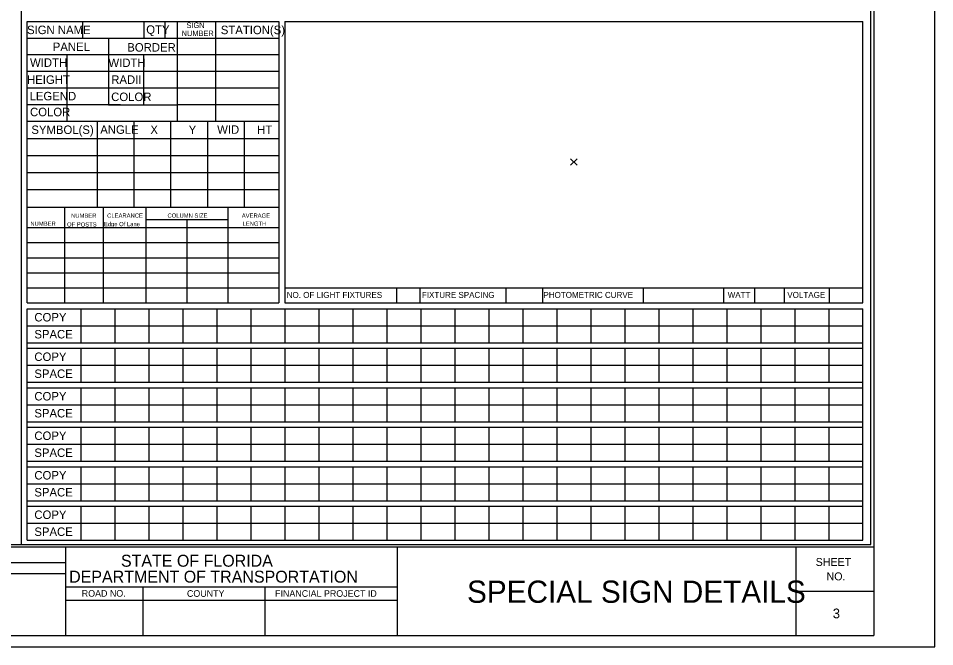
# Model space of a CAD drawing. Extents: x 17890628 to 17891459, y 17897314 to 17897992.
# Drawn here: x 17890765.8 to 17890830.7, y 17897413.7 to 17897458.2 of the extents above; entities that cross this region are included whole.
import ezdxf

# ---------------------------------------------------------------- set-up
doc = ezdxf.new("R2010")
doc.units = 0
for name, color, linetype in [('NonPlottingEle_dp', 7, 'Continuous'), ('PlotBorder_dp', 7, 'Continuous'), ('SheetBorder_dp', 7, 'Continuous'), ('SheetLines_dp', 7, 'Continuous'), ('SheetLinesMisc2_dp', 7, 'Continuous'), ('TextMinor', 7, 'Continuous'), ('TextMisc', 7, 'Continuous'), ('TextShtNo', 7, 'Continuous')]:
    doc.layers.add(name, color=color, linetype=linetype)

msp = doc.modelspace()

# ---------------------------------------------------------------- linework, layer by layer
at = {"layer": 'NonPlottingEle_dp'}
for p, q in [((17890804.948, 17897448.239), (17890805.414, 17897447.773)), ((17890804.948, 17897447.773), (17890805.414, 17897448.239))]:
    msp.add_line(p, q, dxfattribs=at)
at = {"layer": 'PlotBorder_dp'}
msp.add_lwpolyline([(17890701.346, 17897413.687), (17890830.745, 17897413.687), (17890830.745, 17897496.818), (17890701.346, 17897496.818)], close=True, dxfattribs=at)
at = {"layer": 'SheetBorder_dp'}
for p, q in [((17890826.432, 17897496.034), (17890826.432, 17897414.472)), ((17890705.659, 17897420.746), (17890826.432, 17897420.746)), ((17890705.659, 17897414.472), (17890826.432, 17897414.472))]:
    msp.add_line(p, q, dxfattribs=at)
at = {"layer": 'SheetLines_dp'}
for p, q in [((17890769.182, 17897420.746), (17890769.182, 17897414.472)), ((17890792.71, 17897414.471), (17890792.71, 17897420.745)), ((17890820.943, 17897414.471), (17890820.943, 17897420.745)), ((17890705.659, 17897419.648), (17890769.182, 17897419.648)), ((17890705.659, 17897418.864), (17890769.182, 17897418.864)), ((17890769.182, 17897417.923), (17890792.71, 17897417.923)), ((17890774.672, 17897417.923), (17890774.672, 17897414.472)), ((17890783.299, 17897417.923), (17890783.299, 17897414.472)), ((17890820.942, 17897417.609), (17890826.432, 17897417.609)), ((17890769.182, 17897416.981), (17890792.71, 17897416.981))]:
    msp.add_line(p, q, dxfattribs=at)
at = {"layer": 'SheetLinesMisc2_dp'}
for p, q in [((17890766.047, 17897495.849), (17890766.047, 17897420.931)), ((17890826.223, 17897420.931), (17890826.223, 17897495.848)), ((17890766.46, 17897438.022), (17890766.46, 17897457.96)), ((17890766.46, 17897457.96), (17890784.305, 17897457.96)), ((17890770.394, 17897457.96), (17890770.394, 17897456.783)), ((17890774.731, 17897457.96), (17890774.731, 17897456.783)), ((17890776.213, 17897457.96), (17890776.213, 17897456.783)), ((17890777.096, 17897457.96), (17890777.096, 17897450.894)), ((17890779.811, 17897457.96), (17890779.811, 17897450.894)), ((17890784.305, 17897457.96), (17890784.305, 17897438.022)), ((17890784.715, 17897457.96), (17890825.647, 17897457.96)), ((17890784.715, 17897457.96), (17890784.715, 17897438.051)), ((17890825.647, 17897438.051), (17890825.647, 17897457.962)), ((17890766.46, 17897456.783), (17890784.305, 17897456.783)), ((17890772.227, 17897456.783), (17890772.227, 17897452.059)), ((17890766.46, 17897455.605), (17890784.305, 17897455.605)), ((17890769.28, 17897455.605), (17890769.28, 17897450.894)), ((17890774.716, 17897455.592), (17890774.716, 17897452.059)), ((17890766.46, 17897454.427), (17890784.305, 17897454.427)), ((17890766.46, 17897453.25), (17890784.305, 17897453.25)), ((17890766.46, 17897452.072), (17890773.078, 17897452.072)), ((17890772.227, 17897452.059), (17890777.096, 17897452.059)), ((17890777.096, 17897452.072), (17890784.305, 17897452.072)), ((17890766.46, 17897450.894), (17890784.305, 17897450.894)), ((17890771.416, 17897450.871), (17890771.416, 17897444.858)), ((17890774.023, 17897450.871), (17890774.023, 17897444.858)), ((17890776.631, 17897450.871), (17890776.631, 17897444.858)), ((17890779.238, 17897450.871), (17890779.238, 17897444.858)), ((17890781.845, 17897450.871), (17890781.845, 17897444.858)), ((17890766.464, 17897449.668), (17890784.305, 17897449.668)), ((17890766.464, 17897448.466), (17890784.305, 17897448.466)), ((17890766.464, 17897447.263), (17890784.305, 17897447.263)), ((17890766.464, 17897446.061), (17890784.305, 17897446.061)), ((17890766.46, 17897444.801), (17890784.305, 17897444.801)), ((17890769.108, 17897444.801), (17890769.108, 17897438.022)), ((17890771.845, 17897444.801), (17890771.845, 17897438.022)), ((17890774.867, 17897444.801), (17890774.867, 17897438.022)), ((17890780.687, 17897444.801), (17890780.687, 17897438.022)), ((17890774.867, 17897443.939), (17890780.682, 17897443.939)), ((17890777.789, 17897443.939), (17890777.789, 17897438.022)), ((17890766.46, 17897443.363), (17890784.305, 17897443.363)), ((17890766.46, 17897442.295), (17890784.305, 17897442.295)), ((17890766.46, 17897441.227), (17890784.305, 17897441.227)), ((17890766.46, 17897440.159), (17890784.305, 17897440.159)), ((17890766.46, 17897439.091), (17890784.305, 17897439.091)), ((17890784.715, 17897439.091), (17890825.647, 17897439.091)), ((17890792.621, 17897439.091), (17890792.621, 17897438.023)), ((17890794.278, 17897439.091), (17890794.278, 17897438.023)), ((17890800.373, 17897439.091), (17890800.373, 17897438.023)), ((17890802.967, 17897439.091), (17890802.967, 17897438.023)), ((17890810.093, 17897439.091), (17890810.093, 17897438.023)), ((17890815.782, 17897439.091), (17890815.782, 17897438.023)), ((17890817.978, 17897439.091), (17890817.978, 17897438.023)), ((17890820.095, 17897439.091), (17890820.095, 17897438.023)), ((17890823.283, 17897439.091), (17890823.283, 17897438.023)), ((17890766.46, 17897438.022), (17890784.305, 17897438.022)), ((17890784.715, 17897438.051), (17890784.715, 17897438.024)), ((17890784.715, 17897438.023), (17890825.647, 17897438.023)), ((17890825.647, 17897438.024), (17890825.647, 17897438.051)), ((17890766.458, 17897437.612), (17890825.647, 17897437.612)), ((17890766.458, 17897421.223), (17890766.458, 17897437.612)), ((17890770.269, 17897437.612), (17890770.269, 17897435.207)), ((17890772.677, 17897437.612), (17890772.677, 17897435.207)), ((17890775.084, 17897437.612), (17890775.084, 17897435.207)), ((17890777.492, 17897437.612), (17890777.492, 17897435.207)), ((17890779.9, 17897437.612), (17890779.9, 17897435.207)), ((17890782.308, 17897437.612), (17890782.308, 17897435.207)), ((17890784.715, 17897437.612), (17890784.715, 17897435.207)), ((17890787.123, 17897437.612), (17890787.123, 17897435.207)), ((17890789.531, 17897437.612), (17890789.531, 17897435.207)), ((17890791.939, 17897437.612), (17890791.939, 17897435.207)), ((17890794.347, 17897437.612), (17890794.347, 17897435.207)), ((17890796.754, 17897437.612), (17890796.754, 17897435.207)), ((17890799.162, 17897437.612), (17890799.162, 17897435.207)), ((17890801.57, 17897437.612), (17890801.57, 17897435.207)), ((17890803.977, 17897437.612), (17890803.977, 17897435.207)), ((17890806.385, 17897437.612), (17890806.385, 17897435.207)), ((17890808.793, 17897437.612), (17890808.793, 17897435.207)), ((17890811.201, 17897437.612), (17890811.201, 17897435.207)), ((17890813.608, 17897437.612), (17890813.608, 17897435.207)), ((17890816.016, 17897437.612), (17890816.016, 17897435.207)), ((17890818.424, 17897437.612), (17890818.424, 17897435.207)), ((17890820.832, 17897437.612), (17890820.832, 17897435.207)), ((17890823.239, 17897437.612), (17890823.239, 17897435.207)), ((17890825.647, 17897421.223), (17890825.647, 17897437.612)), ((17890766.458, 17897436.411), (17890825.647, 17897436.411)), ((17890766.458, 17897435.207), (17890825.647, 17897435.207)), ((17890766.458, 17897434.815), (17890825.647, 17897434.815)), ((17890770.269, 17897434.815), (17890770.269, 17897432.41)), ((17890772.677, 17897434.815), (17890772.677, 17897432.41)), ((17890775.084, 17897434.815), (17890775.084, 17897432.41)), ((17890777.492, 17897434.815), (17890777.492, 17897432.41)), ((17890779.9, 17897434.815), (17890779.9, 17897432.41)), ((17890782.308, 17897434.815), (17890782.308, 17897432.41)), ((17890784.715, 17897434.815), (17890784.715, 17897432.41)), ((17890787.123, 17897434.815), (17890787.123, 17897432.41)), ((17890789.531, 17897434.815), (17890789.531, 17897432.41)), ((17890791.939, 17897434.815), (17890791.939, 17897432.41)), ((17890794.347, 17897434.815), (17890794.347, 17897432.41)), ((17890796.754, 17897434.815), (17890796.754, 17897432.41)), ((17890799.162, 17897434.815), (17890799.162, 17897432.41)), ((17890801.57, 17897434.815), (17890801.57, 17897432.41)), ((17890803.977, 17897434.815), (17890803.977, 17897432.41)), ((17890806.385, 17897434.815), (17890806.385, 17897432.41)), ((17890808.793, 17897434.815), (17890808.793, 17897432.41)), ((17890811.201, 17897434.815), (17890811.201, 17897432.41)), ((17890813.608, 17897434.815), (17890813.608, 17897432.41)), ((17890816.016, 17897434.815), (17890816.016, 17897432.41)), ((17890818.424, 17897434.815), (17890818.424, 17897432.41)), ((17890820.832, 17897434.815), (17890820.832, 17897432.41)), ((17890823.239, 17897434.815), (17890823.239, 17897432.41)), ((17890766.458, 17897433.613), (17890825.647, 17897433.613)), ((17890766.458, 17897432.41), (17890825.647, 17897432.41)), ((17890766.458, 17897432.018), (17890825.647, 17897432.018)), ((17890770.269, 17897432.018), (17890770.269, 17897429.614)), ((17890772.677, 17897432.018), (17890772.677, 17897429.614)), ((17890775.084, 17897432.018), (17890775.084, 17897429.614)), ((17890777.492, 17897432.018), (17890777.492, 17897429.614)), ((17890779.9, 17897432.018), (17890779.9, 17897429.614)), ((17890782.308, 17897432.018), (17890782.308, 17897429.614)), ((17890784.715, 17897432.018), (17890784.715, 17897429.614)), ((17890787.123, 17897432.018), (17890787.123, 17897429.614)), ((17890789.531, 17897432.018), (17890789.531, 17897429.614)), ((17890791.939, 17897432.018), (17890791.939, 17897429.614)), ((17890794.347, 17897432.018), (17890794.347, 17897429.614)), ((17890796.754, 17897432.018), (17890796.754, 17897429.614)), ((17890799.162, 17897432.018), (17890799.162, 17897429.614)), ((17890801.57, 17897432.018), (17890801.57, 17897429.614)), ((17890803.977, 17897432.018), (17890803.977, 17897429.614)), ((17890806.385, 17897432.018), (17890806.385, 17897429.614)), ((17890808.793, 17897432.018), (17890808.793, 17897429.614)), ((17890811.201, 17897432.018), (17890811.201, 17897429.614)), ((17890813.608, 17897432.018), (17890813.608, 17897429.614)), ((17890816.016, 17897432.018), (17890816.016, 17897429.614)), ((17890818.424, 17897432.018), (17890818.424, 17897429.614)), ((17890820.832, 17897432.018), (17890820.832, 17897429.614)), ((17890823.239, 17897432.018), (17890823.239, 17897429.614)), ((17890766.458, 17897430.816), (17890825.647, 17897430.816)), ((17890766.458, 17897429.614), (17890825.647, 17897429.614)), ((17890766.458, 17897429.221), (17890825.647, 17897429.221)), ((17890770.269, 17897429.221), (17890770.269, 17897426.817)), ((17890772.677, 17897429.221), (17890772.677, 17897426.817)), ((17890775.084, 17897429.221), (17890775.084, 17897426.817)), ((17890777.492, 17897429.221), (17890777.492, 17897426.817)), ((17890779.9, 17897429.221), (17890779.9, 17897426.817)), ((17890782.308, 17897429.221), (17890782.308, 17897426.817)), ((17890784.715, 17897429.221), (17890784.715, 17897426.817)), ((17890787.123, 17897429.221), (17890787.123, 17897426.817)), ((17890789.531, 17897429.221), (17890789.531, 17897426.817)), ((17890791.939, 17897429.221), (17890791.939, 17897426.817)), ((17890794.347, 17897429.221), (17890794.347, 17897426.817)), ((17890796.754, 17897429.221), (17890796.754, 17897426.817)), ((17890799.162, 17897429.221), (17890799.162, 17897426.817)), ((17890801.57, 17897429.221), (17890801.57, 17897426.817)), ((17890803.977, 17897429.221), (17890803.977, 17897426.817)), ((17890806.385, 17897429.221), (17890806.385, 17897426.817)), ((17890808.793, 17897429.221), (17890808.793, 17897426.817)), ((17890811.201, 17897429.221), (17890811.201, 17897426.817)), ((17890813.608, 17897429.221), (17890813.608, 17897426.817)), ((17890816.016, 17897429.221), (17890816.016, 17897426.817)), ((17890818.424, 17897429.221), (17890818.424, 17897426.817)), ((17890820.832, 17897429.221), (17890820.832, 17897426.817)), ((17890823.239, 17897429.221), (17890823.239, 17897426.817)), ((17890766.458, 17897428.02), (17890825.647, 17897428.02)), ((17890766.458, 17897426.817), (17890825.647, 17897426.817)), ((17890766.458, 17897426.424), (17890825.647, 17897426.424)), ((17890770.269, 17897426.424), (17890770.269, 17897424.02)), ((17890772.677, 17897426.424), (17890772.677, 17897424.02)), ((17890775.084, 17897426.424), (17890775.084, 17897424.02)), ((17890777.492, 17897426.424), (17890777.492, 17897424.02)), ((17890779.9, 17897426.424), (17890779.9, 17897424.02)), ((17890782.308, 17897426.424), (17890782.308, 17897424.02)), ((17890784.715, 17897426.424), (17890784.715, 17897424.02)), ((17890787.123, 17897426.424), (17890787.123, 17897424.02)), ((17890789.531, 17897426.424), (17890789.531, 17897424.02)), ((17890791.939, 17897426.424), (17890791.939, 17897424.02)), ((17890794.347, 17897426.424), (17890794.347, 17897424.02)), ((17890796.754, 17897426.424), (17890796.754, 17897424.02)), ((17890799.162, 17897426.424), (17890799.162, 17897424.02)), ((17890801.57, 17897426.424), (17890801.57, 17897424.02)), ((17890803.977, 17897426.424), (17890803.977, 17897424.02)), ((17890806.385, 17897426.424), (17890806.385, 17897424.02)), ((17890808.793, 17897426.424), (17890808.793, 17897424.02)), ((17890811.201, 17897426.424), (17890811.201, 17897424.02)), ((17890813.608, 17897426.424), (17890813.608, 17897424.02)), ((17890816.016, 17897426.424), (17890816.016, 17897424.02)), ((17890818.424, 17897426.424), (17890818.424, 17897424.02)), ((17890820.832, 17897426.424), (17890820.832, 17897424.02)), ((17890823.239, 17897426.424), (17890823.239, 17897424.02)), ((17890766.458, 17897425.222), (17890825.647, 17897425.222)), ((17890766.458, 17897424.02), (17890825.647, 17897424.02)), ((17890766.458, 17897423.628), (17890825.647, 17897423.628)), ((17890770.269, 17897423.628), (17890770.269, 17897421.223)), ((17890772.677, 17897423.628), (17890772.677, 17897421.223)), ((17890775.084, 17897423.628), (17890775.084, 17897421.223)), ((17890777.492, 17897423.628), (17890777.492, 17897421.223)), ((17890779.9, 17897423.628), (17890779.9, 17897421.223)), ((17890782.308, 17897423.628), (17890782.308, 17897421.223)), ((17890784.715, 17897423.628), (17890784.715, 17897421.223)), ((17890787.123, 17897423.628), (17890787.123, 17897421.223)), ((17890789.531, 17897423.628), (17890789.531, 17897421.223)), ((17890791.939, 17897423.628), (17890791.939, 17897421.223)), ((17890794.347, 17897423.628), (17890794.347, 17897421.223)), ((17890796.754, 17897423.628), (17890796.754, 17897421.223)), ((17890799.162, 17897423.628), (17890799.162, 17897421.223)), ((17890801.57, 17897423.628), (17890801.57, 17897421.223)), ((17890803.977, 17897423.628), (17890803.977, 17897421.223)), ((17890806.385, 17897423.628), (17890806.385, 17897421.223)), ((17890808.793, 17897423.628), (17890808.793, 17897421.223)), ((17890811.201, 17897423.628), (17890811.201, 17897421.223)), ((17890813.608, 17897423.628), (17890813.608, 17897421.223)), ((17890816.016, 17897423.628), (17890816.016, 17897421.223)), ((17890818.424, 17897423.628), (17890818.424, 17897421.223)), ((17890820.832, 17897423.628), (17890820.832, 17897421.223)), ((17890823.239, 17897423.628), (17890823.239, 17897421.223)), ((17890766.458, 17897422.425), (17890825.647, 17897422.425)), ((17890705.872, 17897420.931), (17890826.223, 17897420.931)), ((17890766.458, 17897421.223), (17890825.647, 17897421.223))]:
    msp.add_line(p, q, dxfattribs=at)

# ---------------------------------------------------------------- texts
at = {"layer": 'TextMinor'}
for s, height, p in [('SIGN', 0.3921, (17890777.751, 17897457.488)), ('SIGN NAME', 0.5999, (17890766.46, 17897457.059)), ('QTY', 0.5999, (17890774.902, 17897457.078)), ('NUMBER', 0.3921, (17890777.41, 17897456.918)), ('STATION(S)', 0.5999, (17890780.186, 17897457.055)), ('PANEL', 0.5999, (17890768.284, 17897455.862)), ('BORDER', 0.5999, (17890773.561, 17897455.821)), ('WIDTH', 0.5999, (17890766.672, 17897454.741)), ('WIDTH', 0.5999, (17890772.227, 17897454.729)), ('HEIGHT', 0.5999, (17890766.46, 17897453.534)), ('RADII', 0.5999, (17890772.424, 17897453.536)), ('LEGEND', 0.5999, (17890766.64, 17897452.369)), ('COLOR', 0.5999, (17890772.42, 17897452.318)), ('COLOR', 0.5999, (17890766.672, 17897451.245)), ('SYMBOL(S)', 0.5999, (17890766.767, 17897449.987)), ('ANGLE', 0.5999, (17890771.645, 17897449.999)), ('X', 0.6, (17890775.196, 17897449.987)), ('Y', 0.6, (17890777.908, 17897449.987)), ('WID', 0.5999, (17890779.927, 17897449.999)), ('HT', 0.5999, (17890782.753, 17897449.988)), ('NUMBER', 0.3, (17890769.579, 17897444.057)), ('CLEARANCE', 0.3, (17890772.133, 17897444.059)), ('COLUMN SIZE', 0.29998, (17890776.408, 17897444.059)), ('AVERAGE', 0.3, (17890781.669, 17897444.059)), ('NUMBER', 0.3, (17890766.696, 17897443.49)), ('OF POSTS', 0.3, (17890769.295, 17897443.434)), ('Edge Of Lane', 0.29998, (17890771.902, 17897443.456)), ('LENGTH', 0.3, (17890781.726, 17897443.49)), ('NO. OF LIGHT FIXTURES', 0.42516, (17890784.852, 17897438.381)), ('FIXTURE SPACING', 0.42516, (17890794.425, 17897438.381)), ('PHOTOMETRIC CURVE', 0.42516, (17890803.034, 17897438.381)), ('WATT', 0.4252, (17890816.086, 17897438.381)), ('VOLTAGE', 0.4252, (17890820.307, 17897438.381)), ('COPY', 0.6, (17890766.979, 17897436.713)), ('SPACE', 0.6, (17890766.979, 17897435.511)), ('COPY', 0.6, (17890766.979, 17897433.915)), ('SPACE', 0.6, (17890766.979, 17897432.713)), ('COPY', 0.6, (17890766.979, 17897431.119)), ('SPACE', 0.6, (17890766.979, 17897429.917)), ('COPY', 0.6, (17890766.979, 17897428.321)), ('SPACE', 0.6, (17890766.979, 17897427.12)), ('COPY', 0.6, (17890766.979, 17897425.524)), ('SPACE', 0.6, (17890766.979, 17897424.322)), ('COPY', 0.6, (17890766.979, 17897422.728)), ('SPACE', 0.6, (17890766.979, 17897421.526))]:
    msp.add_text(s, height=height, dxfattribs=at).set_placement(p)
at = {"layer": 'TextMisc'}
for s, height, p in [('STATE OF FLORIDA', 0.84699, (17890773.111, 17897419.348)), ('DEPARTMENT OF TRANSPORTATION', 0.84699, (17890769.441, 17897418.219)), ('SPECIAL SIGN DETAILS', 1.57464, (17890797.624, 17897416.792)), ('ROAD NO.', 0.4705, (17890770.336, 17897417.224)), ('COUNTY', 0.4705, (17890777.786, 17897417.216)), ('FINANCIAL PROJECT ID', 0.47055, (17890784.029, 17897417.216))]:
    msp.add_text(s, height=height, dxfattribs=at).set_placement(p)
for s, p in [('SHEET', (17890822.315, 17897419.404)), ('NO.', (17890823.084, 17897418.384))]:
    msp.add_text(s, height=0.5647, rotation=359.86066, dxfattribs=at).set_placement(p)
at = {"layer": 'TextShtNo'}
msp.add_text('3', height=0.69, dxfattribs=at).set_placement((17890823.528, 17897415.695))

doc.saveas('drawing.dxf')
